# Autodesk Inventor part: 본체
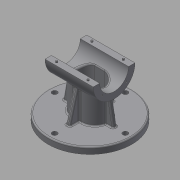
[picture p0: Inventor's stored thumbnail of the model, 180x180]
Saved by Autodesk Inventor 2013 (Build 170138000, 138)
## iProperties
Created: 2015-12
Part Number: 본체
Material: 일반
Document SubType Name: Modeling
Designer: mduedu
Density: 2.71 g/cm^3
Author: mduedu
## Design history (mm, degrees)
sketch "스케치1"
  geometry: C1 r 65 at (0, 0); 1 further point
  constraints: 1 centre point, 1 coincident
  dimensions: "d124" = 130 diameter of C1
extrude "돌출1" new body sketch "스케치1" distance "d3" = 10; taper "d4" = 0 deg
sketch "스케치2"
  geometry: C1 r 32.5 at (80, 0); 1 further point
  constraints: 1 centre point, 1 horizontal alignment
  dimensions: "d5" = 65 diameter of C1; "d125" = 80 distance of C1.centre point (0, 0)
extrude "돌출2" join sketch "스케치2" stored distance "d7" = 75; taper "d8" = 0 deg
sketch "스케치3"
  geometry: L1 (-27.5, -20)-(27.5, -20); L2 (27.5, -20)-(27.5, 20); L3 (27.5, 20)-(-27.5, 20); L4 (-27.5, 20)-(-27.5, -20); L5 (-27.5, -20)-(27.5, 20); L6 (27.5, -20)-(-27.5, 20); 1 further point
  constraints: 12 end point, 2 midpoint, 2 parallel, 1 horizontal, 1 perpendicular
  dimensions: "d9" = 55 distance of L2.end L3.end; "d11" = 40 distance of L1.end L2.end
extrude "돌출3" new body sketch "스케치3" stored distance "d12" = 75; taper "d13" = 0 deg
fillet "모깎기1"
fillet "모깎기2"
feature "결합1"
  node "솔리드2"
sketch "스케치4"
  geometry: L1 (-37.5, 47.5)-(37.5, 47.5) reference; L2 (32.5, 47.5)-(39.112, 10); L3 (37.5, 47.5)-(37.5, 112.5) reference; L4 (65, 10)-(-65, 10) reference; 1 further point
  constraints: 2 end point, 2 point on line
  dimensions: "d15" = 5 distance from line of L2.start L3; "d126" = 80 deg angle of L2 L1
sketch "스케치5"
  geometry: L1 (10, 35)-(56.569, 22.522); L2 (10, -65)-(10, 65) reference; L3 (10, 20)-(54.383, 20) reference; A1 r 32.5 centre (80, 0) between (56.569, 22.522) and (54.383, 20) reference; 1 further point
  constraints: 2 end point, 1 point on circle, 1 point on line
  dimensions: "d127" = 75 deg angle of L1 L2; "d128" = 15 distance of L1.start L3.start
feature "리브1" dims "d19" = 1, "d20" = 6, "d21" = 0, "d22" = 0, "d23" = 1, "d24" = 1
feature "리브2" dims "d25" = 1, "d26" = 6, "d27" = 0, "d28" = 0, "d29" = 1, "d30" = 1
fillet "모깎기4" dims "d31" = 2
fillet "모깎기5" dims "d32" = 2
fillet "모깎기6" dims "d33" = 2
fillet "모깎기7" dims "d41" = 2
hole "구멍2" diameter "d44" = 45; stored, may be unused: countersink angle "d48" = 90 deg, drill point angle "d50" = 118 deg; dims "d42" = 10, "d43" = 10, "d45" = 6, "d46" = 4, "d47" = 2, "d49" = 8
sketch "스케치7" dims "d52" = 26.5
  geometry: L1 (0, 0)-(32.5, 0); L2 (0, 0)-(22.981, 22.981); A1 r 32.5 centre (0, 0) between (32.5, 0) and (22.981, 22.981) reference; 3 further points
  constraints: 4 end point, 2 point on circle, 1 coincident, 1 horizontal, 1 point on line, 3 other
  dimensions: "d51" = 45 deg angle of L2 L1
hole "구멍3" sketch "스케치7" at (18.738, 18.738) diameter "d54" = 2.459; stored, may be unused: countersink angle "d58" = 90 deg, drill point angle "d60" = 118 deg; dims "d55" = 8, "d56" = 4, "d57" = 2, "d59" = 10
sketch "스케치9"
  geometry: L1 (-75, 82.5)-(75, 82.5); L2 (75, 82.5)-(75, 0); L3 (75, 0)-(-75, 0); L4 (-75, 0)-(-75, 82.5); C1 r 32.5 at (0, 0) reference; 2 further points
  constraints: 8 end point, 2 parallel, 1 coincident, 1 horizontal, 1 midpoint, 1 perpendicular
  dimensions: "d71" = 50 distance edge to line of C1 L1; "d116" = 150 distance between parallel lines of L2 L4
extrude "돌출5" cut sketch "스케치9" stored distance "d73" = 0; taper "d74" = 0 deg
node "작업 평면1"
sketch "스케치10"
  geometry: L1 (-7.5, 15)-(7.5, 15); L2 (-7.5, -15)-(7.5, -15); A1 r 20 centre (-7.5, 0) between (-7.5, 20) and (-26.977, 4.545) reference; A2 r 20 centre (7.5, 0) between (26.977, 4.545) and (7.5, 20) reference; A3 r 15 centre (-7.5, 0) between (-7.5, 15) and (-7.5, -15); A4 r 15 centre (7.5, 0) between (7.5, -15) and (7.5, 15); 1 further point
  constraints: 7 point on circle, 4 end point, 4 tangent, 3 point on line, 2 centre point, 2 coincident, 1 horizontal
  dimensions: "d77" = 5 radial gap between concentric circles of A3 A1
extrude "돌출6" cut sketch "스케치10" stored distance "d78" = 50; taper "d79" = 0 deg
fillet "모깎기10" dims "d80" = 3
sketch "스케치11"
  geometry: 2 further points
  constraints: 1 coincident
hole "구멍4" sketch "스케치11" at (0, 0) diameter "d81" = 12; stored, may be unused: countersink angle "d85" = 90 deg, drill point angle "d87" = 118 deg; dims "d82" = 8, "d83" = 40, "d84" = 10, "d86" = 10
sketch "스케치12"
  geometry: C1 r 10 at (0, 0); 1 further point
  constraints: 1 centre point, 1 coincident
  dimensions: "d88" = 20 diameter of C1
extrude "돌출7" cut sketch "스케치12" distance "d89" = 5; taper "d90" = 0 deg
chamfer "모따기1" distance "d91" = 1; stored, may be unused: second distance "d92" = 2, angle "d93" = 45 deg
fillet "모깎기11" dims "d94" = 0.5
fillet "모깎기12" dims "d115" = 0.3
sketch "스케치15"
  geometry: L1 (-75, 55)-(-75, 65) reference; L2 (0, 65)-(0, 55) reference; L3 (-75, 60)-(0, 60); C1 r 1.5 at (-62, 60); 1 further point
  constraints: 2 end point, 2 midpoint, 1 centre point, 1 point on line
  dimensions: "d117" = 3 diameter of C1; "d118" = 13 distance from line of C1.centre L1
extrude "돌출8" join sketch "스케치15" distance "d119" = 1.8; taper "d120" = 0 deg
chamfer "모따기2" distance "d121" = 0.5; stored, may be unused: second distance "d122" = 2, angle "d123" = 45 deg
sketch "스케치18" dims "d141" = 110
  geometry: C1 r 63 at (0, 0) reference; 2 further points
  constraints: 2 vertical alignment, 1 coincident, 2 other
hole "구멍8" sketch "스케치18" at (0, 55) diameter "d142" = 8; stored, may be unused: countersink angle "d146" = 90 deg, drill point angle "d148" = 118 deg; dims "d143" = 6, "d144" = 4, "d145" = 2, "d147" = 8
node "솔리드1"
mirror "대칭1"
mirror "대칭2"
pattern_circular "원형 패턴1" dims angle "d62" = 360 deg
mirror "대칭3"
mirror "대칭5"
mirror "대칭6"
pattern_circular "원형 패턴2" dims angle "d150" = 360 deg
mirror "대칭7"
